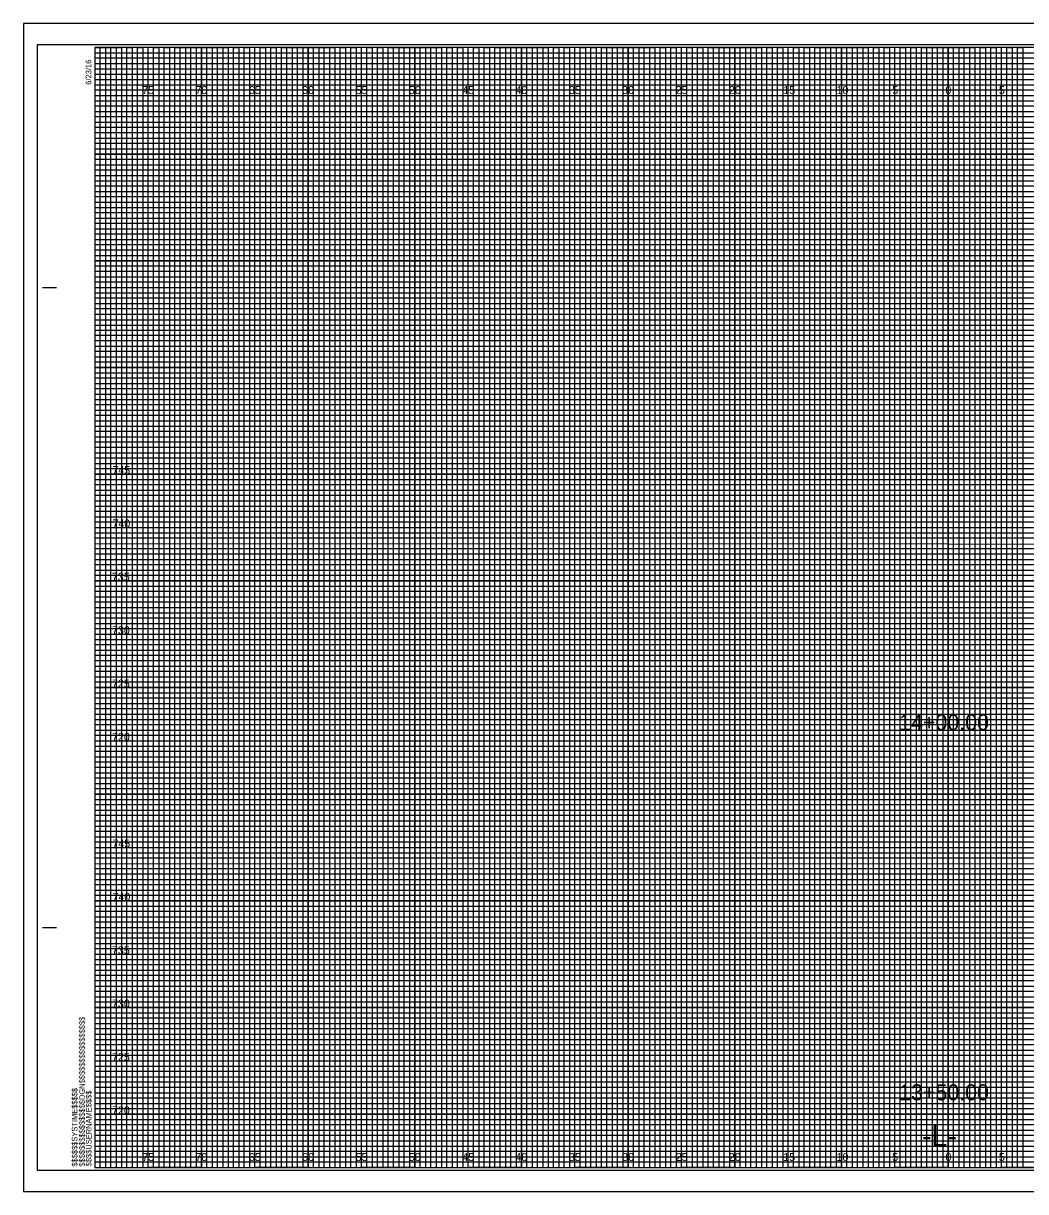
# Model space of a CAD drawing. Extents: x -7 to 183, y -2 to 107.
# Drawn here: x -6.7 to 87.2, y -2.2 to 107.2 of the extents above; entities that cross this region are included whole.
import ezdxf

# ---------------------------------------------------------------- set-up
doc = ezdxf.new("R2010")
doc.units = 0
for name, color, linetype in [('Prop XS Alignment Label', 7, 'Continuous'), ('Prop XS Elevation Labels', 7, 'Continuous'), ('Prop XS Offset Labels', 7, 'Continuous'), ('Prop XS Station Labels', 7, 'Continuous'), ('Sheet Cross Section CELL', 7, 'Continuous'), ('Sheet Cross Section Grid Major CELL', 7, 'Continuous'), ('Sheet Cross Section Grid Middle CELL', 7, 'Continuous'), ('Sheet Cross Section Grid Minor 1 CELL', 7, 'Continuous'), ('Sheet Cross Section Grid Minor 2 CELL', 7, 'Continuous'), ('Sheet Cutting Line CELL', 7, 'Continuous'), ('Sheet DOT Grid CELL', 7, 'Continuous'), ('Sheet Plot Border Inside CELL', 7, 'Continuous'), ('Sheet Plot Border Outside CELL', 7, 'Continuous')]:
    doc.layers.add(name, color=color, linetype=linetype)

msp = doc.modelspace()

# ---------------------------------------------------------------- linework, layer by layer
at = {"layer": 'Sheet Cross Section CELL'}
for p, q in [((-4.9, 82.5), (-3.65, 82.5)), ((-4.85, 82.5), (-3.6, 82.5)), ((-4.9, 22.5), (-3.65, 22.5)), ((-4.85, 22.5), (-3.6, 22.5)), ((0, 0), (0, 0)), ((0, 0), (0, 0)), ((0, 0), (0, 0)), ((0, 0), (0, 0)), ((0, 0), (0, 0)), ((0, 0), (0, 0)), ((0, 0), (0, 0))]:
    msp.add_line(p, q, dxfattribs=at)
msp.add_lwpolyline([(160, 105), (0, 105), (0, 0), (160, 0)], close=True, dxfattribs=at)
at = {"layer": 'Sheet Cross Section Grid Major CELL'}
for p, q in [((5, 105), (0, 105)), ((5, 0), (5, 105)), ((15, 105), (10, 105)), ((10, 105), (10, 0)), ((15, 0), (15, 105)), ((25, 105), (20, 105)), ((20, 105), (20, 0)), ((25, 0), (25, 105)), ((35, 105), (30, 105)), ((30, 105), (30, 0)), ((35, 0), (35, 105)), ((45, 105), (40, 105)), ((40, 105), (40, 0)), ((45, 0), (45, 105)), ((55, 105), (50, 105)), ((50, 105), (50, 0)), ((55, 0), (55, 105)), ((65, 105), (60, 105)), ((60, 105), (60, 0)), ((65, 0), (65, 105)), ((75, 105), (70, 105)), ((70, 105), (70, 0)), ((75, 0), (75, 105)), ((85, 105), (80, 105)), ((80, 105), (80, 0)), ((85, 0), (85, 105)), ((10, 0), (5, 0)), ((20, 0), (15, 0)), ((30, 0), (25, 0)), ((40, 0), (35, 0)), ((50, 0), (45, 0)), ((60, 0), (55, 0)), ((70, 0), (65, 0)), ((80, 0), (75, 0)), ((90, 0), (85, 0))]:
    msp.add_line(p, q, dxfattribs=at)
for points in [[(0, 100), (160, 100), (160, 95), (0, 95)], [(0, 90), (160, 90), (160, 85), (0, 85)], [(0, 80), (160, 80), (160, 75), (0, 75)], [(0, 70), (160, 70), (160, 65), (0, 65)], [(0, 60), (160, 60), (160, 55), (0, 55)], [(0, 50), (160, 50), (160, 45), (0, 45)], [(0, 40), (160, 40), (160, 35), (0, 35)], [(0, 30), (160, 30), (160, 25), (0, 25)], [(0, 20), (160, 20), (160, 15), (0, 15)], [(0, 10), (160, 10), (160, 5), (0, 5)]]:
    msp.add_lwpolyline(points, dxfattribs=at)
at = {"layer": 'Sheet Cross Section Grid Middle CELL'}
for points in [[(0, 105), (2.5, 105), (2.5, 0), (7.5, 0), (7.5, 105), (12.5, 105), (12.5, 0), (17.5, 0), (17.5, 105), (22.5, 105), (22.5, 0), (27.5, 0), (27.5, 105), (32.5, 105), (32.5, 0), (37.5, 0), (37.5, 105), (42.5, 105), (42.5, 0), (47.5, 0), (47.5, 105), (52.5, 105), (52.5, 0), (57.5, 0), (57.5, 105), (62.5, 105), (62.5, 0), (67.5, 0), (67.5, 105), (72.5, 105), (72.5, 0), (77.5, 0), (77.5, 105), (82.5, 105), (82.5, 0), (87.5, 0)], [(0, 102.5), (137.5, 102.5)], [(0, 92.5), (160, 92.5), (160, 97.5), (0, 97.5)], [(0, 82.5), (160, 82.5), (160, 87.5), (0, 87.5)], [(0, 72.5), (160, 72.5), (160, 77.5), (0, 77.5)], [(0, 62.5), (160, 62.5), (160, 67.5), (0, 67.5)], [(0, 52.5), (160, 52.5), (160, 57.5), (0, 57.5)], [(0, 42.5), (160, 42.5), (160, 47.5), (0, 47.5)], [(0, 32.5), (160, 32.5), (160, 37.5), (0, 37.5)], [(0, 22.5), (160, 22.5), (160, 27.5), (0, 27.5)], [(0, 12.5), (160, 12.5), (160, 17.5), (0, 17.5)], [(0, 2.5), (160, 2.5), (160, 7.5), (0, 7.5)]]:
    msp.add_lwpolyline(points, dxfattribs=at)
at = {"layer": 'Sheet Cross Section Grid Minor 1 CELL'}
for p, q in [((0, 104.5), (130, 104.5)), ((130, 103.99), (0, 103.99)), ((0, 103.99), (0, 103.5)), ((0, 103.5), (130, 103.5)), ((130, 102.95), (0, 102.95)), ((0, 102.95), (0, 102)), ((0, 102), (160, 102))]:
    msp.add_line(p, q, dxfattribs=at)
for points in [[(0, 101.5), (135, 101.5), (160, 101.5), (160, 101), (0, 101)], [(0, 100.5), (160, 100.5), (160, 99.5), (0, 99.5)], [(0, 99), (160, 99), (160, 98.5), (0, 98.49)], [(0, 98), (160, 98), (160, 97), (0, 97)], [(0, 96.5), (160, 96.5), (160, 96), (0, 96)], [(0, 95.5), (160, 95.5), (160, 94.5), (0, 94.5)], [(0, 94), (160, 94), (160, 93.5), (0, 93.5)], [(0, 93), (160, 93), (160, 92), (0, 92)], [(0, 91.5), (160, 91.5), (160, 91), (0, 91)], [(0, 90.5), (160, 90.5), (160, 89.5), (0, 89.5)], [(0, 89), (160, 89), (160, 88.5), (0, 88.5)], [(0, 88), (160, 88), (160, 86.98), (160, 86.5), (160, 86), (0, 86)], [(0, 87), (160, 87), (160, 86.5), (0, 86.5)], [(0, 85.5), (160, 85.5), (160, 84.5), (0, 84.52)], [(0, 84.52), (160, 84.5), (160, 84), (0, 84)], [(0, 83.5), (160, 83.5), (160, 83), (0, 83)], [(0, 82), (160, 82), (160, 81.5), (0, 81.5)], [(0, 81), (160, 81), (160, 80.5), (0, 80.5)], [(-0.04, 79.45), (160, 79.45), (160, 78.94), (-0.04, 78.94)], [(0, 78.5), (160, 78.5), (160, 78), (0, 78)], [(0, 77), (160, 77), (160, 76.5), (0, 76.5)], [(0, 76), (160, 76), (160, 75.5), (0, 75.5)], [(0, 74.5), (160, 74.5), (160, 74), (0, 74)], [(0, 73.5), (160, 73.5), (160, 73), (0, 73)], [(0, 72), (160, 72), (160, 71.5), (0, 71.5)], [(0, 71), (160, 71), (160, 70.5), (0, 70.5)], [(0, 69.5), (160, 69.5), (160, 68.99), (0, 69)], [(0, 68.5), (160, 68.5), (160, 68), (0, 68)], [(0, 67), (160, 67), (160, 66.5), (0, 66.5)], [(0, 66), (160, 66), (160, 65.5), (0, 65.5)], [(0, 64.5), (160, 64.5), (160, 64), (0, 64)], [(0, 63.5), (160, 63.5), (160, 63), (0, 63)], [(0, 62), (160, 62), (160, 61.5), (0, 61.5)], [(0, 61), (160, 61), (160, 60.5), (0, 60.5)], [(0, 59.5), (160, 59.5), (160, 59), (0, 59)], [(0, 58.5), (160.03, 58.45), (160, 58), (0, 58)], [(0, 57), (160, 57), (160, 56.5), (0, 56.5)], [(0, 56), (160, 56), (160, 55.5), (0, 55.5)], [(0, 54.5), (160, 54.5), (160, 54), (0, 54)], [(0, 53.5), (160, 53.5), (160, 53), (0, 53)], [(0, 52), (160, 52), (160, 51.5), (0, 51.5)], [(0, 51), (160, 51), (160, 50.5), (0, 50.5)], [(0, 49.5), (160, 49.5), (160, 49), (0, 49)], [(0, 48.5), (160, 48.5), (160, 48), (0, 48)], [(0, 47), (160, 47), (160, 46.5), (0, 46.5)], [(0, 46), (160, 46), (160, 45.5), (0, 45.5)], [(0, 44.5), (160, 44.5), (160, 44), (0, 44)], [(0, 43.5), (160, 43.5), (160, 43), (0, 43)], [(0, 42), (160, 42), (160, 41.5), (0, 41.5)], [(0, 41), (160, 41), (160, 40.5), (0, 40.5)], [(0, 39.5), (160, 39.5), (160, 38.99), (0, 39)], [(0, 38.5), (160, 38.5), (160, 38), (0, 38)], [(0, 37), (160, 37), (160, 36.5), (0, 36.5)], [(0, 36), (160, 36), (160, 35.5), (0, 35.5)], [(0, 34.5), (160, 34.5), (160, 34), (0, 34)], [(0, 33.5), (160, 33.5), (160, 33), (0, 33)], [(0, 32), (160, 32), (160, 31.5), (0, 31.5)], [(0, 31), (160, 31), (160, 30.5), (0, 30.5)], [(0, 29.5), (160, 29.5), (160, 29), (0, 29)], [(0, 28.5), (160.03, 28.46), (160, 28), (0, 28)], [(0, 27), (160, 27), (160, 26.5), (0, 26.5)], [(0, 26), (160, 26), (160, 25.5), (0, 25.5)], [(0, 24.5), (160, 24.5), (160, 24), (0, 24)], [(0, 23.5), (160, 23.5), (160, 23), (0, 23)], [(0, 22), (160, 22), (160, 21.5), (0, 21.5)], [(0, 21), (160, 21), (160, 20.5), (0, 20.5)], [(0, 19.5), (160, 19.5), (160, 19), (0, 19)], [(0, 18.5), (160, 18.5), (160, 18), (0, 18)], [(0, 17), (160, 17), (160, 16.5), (0, 16.5)], [(0, 16), (160, 16), (160, 15.5), (0, 15.5)], [(0, 14.5), (160, 14.5), (160, 14), (0, 14)], [(0, 13.5), (160, 13.5), (160, 13), (0, 13)], [(0, 12), (160, 12), (160, 11.5), (0, 11.5)], [(0, 11), (160, 11), (160, 10.5), (0, 10.5)], [(0, 9.5), (160, 9.5), (160, 9), (0, 9)], [(0, 8.5), (160, 8.5), (160, 8), (0, 8)], [(0, 7), (160, 7), (160, 6.5), (0, 6.5)], [(0, 6), (160, 6), (160, 5.5), (0, 5.5)], [(0, 4.5), (160, 4.5), (160, 4), (0, 4)], [(0, 3.5), (160, 3.5), (160, 3), (0, 3)], [(0, 2), (160, 2), (160, 1.5), (0, 1.5)], [(0, 1), (160, 1), (160, 0.5), (0, 0.5)]]:
    msp.add_lwpolyline(points, dxfattribs=at)
at = {"layer": 'Sheet Cross Section Grid Minor 2 CELL'}
for points in [[(0, 0), (0.5, 0), (0.5, 105), (1, 105), (1, 0)], [(1, 0), (1.5, 0), (1.5, 105), (2, 105), (2, 0)], [(2.5, 0), (3, 0), (3, 105), (3.5, 105), (3.5, 0)], [(3.5, 0), (4, 0), (4, 105), (4.5, 105), (4.5, 0)], [(5, 0), (5.5, 0), (5.5, 105), (6, 105), (6, 0)], [(6, 0), (6.5, 0), (6.5, 105), (7, 105), (7, 0)], [(7.5, 0), (8, 0), (8, 105), (8.5, 105), (8.5, 0)], [(8.5, 0), (9, 0), (9, 105), (9.5, 105), (9.5, 0)], [(10, 0), (10.5, 0), (10.5, 105), (11, 105), (11, 0)], [(11, 0), (11.5, 0), (11.5, 105), (12, 105), (12, 0)], [(12.5, 0), (13, 0), (13, 105), (13.5, 105), (13.5, 0)], [(13.5, 0), (14, 0), (14, 105), (14.5, 105), (14.5, 0)], [(15, 0), (15.5, 0), (15.5, 105), (16, 105), (16, 0)], [(16, 0), (16.5, 0), (16.5, 105), (17, 105), (17, 0)], [(17.5, 0), (18, 0), (18, 105), (18.5, 105), (18.5, 0)], [(18.5, 0), (19, 0), (19, 105), (19.5, 105), (19.5, 0)], [(20, 0), (20.5, 0), (20.5, 105), (21, 105), (21, 0)], [(21, 0), (21.5, 0), (21.5, 105), (22, 105), (22, 0)], [(22.5, 0), (23, 0), (23, 105), (23.5, 105), (23.5, 0)], [(23.5, 0), (24, 0), (24, 105), (24.5, 105), (24.5, 0)], [(25, 0), (25.5, 0), (25.5, 105), (26, 105), (26, 0)], [(26, 0), (26.5, 0), (26.5, 105), (27, 105), (27, 0)], [(27.5, 0), (28, 0), (28, 105), (28.5, 105), (28.5, 0)], [(28.5, 0), (29, 0), (29, 105), (29.5, 105), (29.5, 0)], [(30, 0), (30.5, 0), (30.5, 105), (31, 105), (31, 0)], [(31, 0), (31.5, 0), (31.5, 105), (32, 105), (32, 0)], [(32.5, 0), (33, 0), (33, 105), (33.5, 105), (33.5, 0)], [(33.5, 0), (34, 0), (34, 105), (34.5, 105), (34.5, 0)], [(35, 0), (35.5, 0), (35.5, 105), (36, 105), (36, 0)], [(36, 0), (36.5, 0), (36.5, 105), (37, 105), (37, 0)], [(37.5, 0), (38, 0), (38, 105), (38.5, 105), (38.5, 0)], [(38.5, 0), (39, 0), (39, 105), (39.5, 105), (39.5, 0)], [(40, 0), (40.5, 0), (40.5, 105), (41, 105), (41, 0)], [(41, 0), (41.5, 0), (41.5, 105), (42, 105), (42, 0)], [(42.5, 0), (43, 0), (43, 105), (43.5, 105), (43.5, 0)], [(43.5, 0), (44, 0), (44, 105), (44.5, 105), (44.5, 0)], [(45, 0), (45.5, 0), (45.5, 105), (46, 105), (46, 0)], [(46, 0), (46.5, 0), (46.5, 105), (47, 105), (47, 0)], [(47.5, 0), (48, 0), (48, 105), (48.5, 105), (48.5, 0)], [(48.5, 0), (49, 0), (49, 105), (49.5, 105), (49.5, 0)], [(50, 0), (50.5, 0), (50.5, 105), (51, 105), (51, 0)], [(51, 0), (51.5, 0), (51.5, 105), (52, 105), (52, 0)], [(52.5, 0), (53, 0), (53, 105), (53.5, 105), (53.5, 0)], [(53.5, 0), (54, 0), (54, 105), (54.5, 105), (54.5, 0)], [(55, 0), (55.5, 0), (55.5, 105), (56, 105), (56, 0)], [(56, 0), (56.5, 0), (56.5, 105), (57, 105), (57, 0)], [(57.5, 0), (58, 0), (58, 105), (58.5, 105), (58.5, 0)], [(58.5, 0), (59, 0), (59, 105), (59.5, 105), (59.5, 0)], [(60, 0), (60.5, 0), (60.5, 105), (61, 105), (61, 0)], [(61, 0), (61.5, 0), (61.5, 105), (62, 105), (62, 0)], [(62.5, 0), (63, 0), (63, 105), (63.5, 105), (63.5, 0)], [(63.5, 0), (64, 0), (64, 105), (64.5, 105), (64.5, 0)], [(65, 0), (65.5, 0), (65.5, 105), (66, 105), (66, 0)], [(66, 0), (66.5, 0), (66.5, 105), (67, 105), (67, 0)], [(67.5, 0), (68, 0), (68, 105), (68.5, 105), (68.5, 0)], [(68.5, 0), (69, 0), (69, 105), (69.5, 105), (69.5, 0)], [(70, 0), (70.5, 0), (70.5, 105), (71, 105), (71, 0)], [(71, 0), (71.5, 0), (71.5, 105), (72, 105), (72, 0)], [(72.5, 0), (73, 0), (73, 105), (73.5, 105), (73.5, 0)], [(73.5, 0), (74, 0), (74, 105), (74.5, 105), (74.5, 0)], [(75, 0), (75.5, 0), (75.5, 105), (76, 105), (76, 0)], [(76, 0), (76.5, 0), (76.5, 105), (77, 105), (77, 0)], [(77.5, 0), (78, 0), (78, 105), (78.5, 105), (78.5, 0)], [(78.5, 0), (79, 0), (79, 105), (79.5, 105), (79.5, 0)], [(80, 0), (80.5, 0), (80.5, 105), (81, 105), (81, 0)], [(81, 0), (81.5, 0), (81.5, 105), (82, 105), (82, 0)], [(82.5, 0), (83, 0), (83, 105), (83.5, 105), (83.5, 0)], [(83.5, 0), (84, 0), (84, 105), (84.5, 105), (84.5, 0)], [(85, 0), (85.5, 0), (85.5, 105), (86, 105), (86, 0)], [(86, 0), (86.5, 0), (86.5, 105), (87, 105), (87, 0)]]:
    msp.add_lwpolyline(points, dxfattribs=at)
at = {"layer": 'Sheet Cutting Line CELL'}
for p, q in [((161.65, 107.25), (-6.7, 107.25)), ((-6.7, 107.25), (-6.7, -2.25)), ((-6.7, -2.25), (161.65, -2.25))]:
    msp.add_line(p, q, dxfattribs=at)
at = {"layer": 'Sheet DOT Grid CELL'}
for p, q in [((5, 0), (5, 105)), ((10, 0), (10, 105)), ((15, 0), (15, 105)), ((20, 0), (20, 105)), ((25, 0), (25, 105)), ((30, 0), (30, 105)), ((35, 0), (35, 105)), ((40, 0), (40, 105)), ((45, 0), (45, 105)), ((50, 0), (50, 105)), ((55, 0), (55, 105)), ((60, 0), (60, 105)), ((65, 0), (65, 105)), ((70, 0), (70, 105)), ((75, 0), (75, 105)), ((80, 0), (80, 105)), ((85, 0), (85, 105)), ((0, 100), (160, 100)), ((0, 95), (160, 95)), ((0, 90), (160, 90)), ((0, 85), (160, 85)), ((0, 80), (160, 80)), ((0, 75), (160, 75)), ((0, 70), (160, 70)), ((0, 65), (160, 65)), ((0, 60), (160, 60)), ((0, 55), (160, 55)), ((0, 50), (160, 50)), ((0, 45), (160, 45)), ((0, 40), (160, 40)), ((0, 35), (160, 35)), ((0, 30), (160, 30)), ((0, 25), (160, 25)), ((0, 20), (160, 20)), ((0, 15), (160, 15)), ((0, 10), (160, 10)), ((0, 5), (160, 5))]:
    msp.add_line(p, q, dxfattribs=at)
at = {"layer": 'Sheet Plot Border Inside CELL'}
msp.add_lwpolyline([(-5.4, -0.25), (161.2, -0.25), (161.2, 105.25), (-5.4, 105.25)], close=True, dxfattribs=at)
at = {"layer": 'Sheet Plot Border Outside CELL'}
msp.add_lwpolyline([(-6.7, -2.25), (161.65, -2.25), (161.65, 107.25), (-6.7, 107.25)], close=True, dxfattribs=at)

# ---------------------------------------------------------------- texts
at = {"layer": 'Prop XS Alignment Label'}
msp.add_text('-L-', height=2, dxfattribs=at).set_placement((77.53, 2))
at = {"layer": 'Prop XS Elevation Labels'}
for s, p in [('745', (1.64, 65)), ('740', (1.65, 60)), ('735', (1.6, 55)), ('730', (1.61, 50)), ('725', (1.61, 45)), ('720', (1.61, 40)), ('745', (1.64, 30)), ('740', (1.65, 25)), ('735', (1.6, 20)), ('730', (1.61, 15)), ('725', (1.61, 10)), ('720', (1.61, 5))]:
    msp.add_text(s, height=0.75, dxfattribs=at).set_placement(p)
at = {"layer": 'Prop XS Offset Labels'}
for s, p in [('75', (4.44, 100.62)), ('70', (9.43, 100.62)), ('65', (14.44, 100.62)), ('60', (19.43, 100.62)), ('55', (24.44, 100.62)), ('50', (29.43, 100.62)), ('45', (34.44, 100.62)), ('40', (39.43, 100.62)), ('35', (44.44, 100.62)), ('30', (49.43, 100.62)), ('25', (54.44, 100.62)), ('20', (59.43, 100.62)), ('15', (64.53, 100.62)), ('10', (69.52, 100.62)), ('5', (74.74, 100.62)), ('0', (79.73, 100.62)), ('0', (79.73, 100.62)), ('5', (84.74, 100.62)), ('75', (4.44, 0.62)), ('70', (9.43, 0.62)), ('65', (14.44, 0.62)), ('60', (19.43, 0.62)), ('55', (24.44, 0.62)), ('50', (29.43, 0.62)), ('45', (34.44, 0.62)), ('40', (39.43, 0.62)), ('35', (44.44, 0.62)), ('30', (49.43, 0.62)), ('25', (54.44, 0.62)), ('20', (59.43, 0.62)), ('15', (64.53, 0.62)), ('10', (69.52, 0.62)), ('5', (74.74, 0.62)), ('0', (79.73, 0.62)), ('0', (79.73, 0.62)), ('5', (84.74, 0.62))]:
    msp.add_text(s, height=0.75, dxfattribs=at).set_placement(p)
at = {"layer": 'Prop XS Station Labels'}
for s, p in [('14+00.00', (75.39, 40.99)), ('13+50.00', (75.39, 6.31))]:
    msp.add_text(s, height=1.5, dxfattribs=at).set_placement(p)
at = {"layer": 'Sheet Cross Section CELL'}
for s, p in [('6/23/16', (-0.33, 101.5)), ('$$$$$$$$$$$$$$$$DGN$$$$$$$$$$$$$$$$', (-0.94, 0.09)), ('$$$$$$SYSTIME$$$$$', (-1.63, 0.09)), ('$$$$USERNAME$$$$', (-0.31, 0.12))]:
    msp.add_text(s, height=0.525, rotation=90, dxfattribs=at).set_placement(p)

doc.saveas('drawing.dxf')
